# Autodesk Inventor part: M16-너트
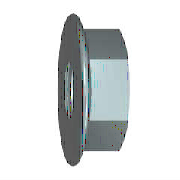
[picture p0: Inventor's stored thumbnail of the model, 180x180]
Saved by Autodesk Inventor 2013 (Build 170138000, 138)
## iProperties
IsCustomPart: 0
Company: 한국ATC센터
Created: 2009-02
Part Number: M16-너트
Material: Steel, Mild
Description: 플랜지붙이 6각 너트
Document SubType Name: Modeling
Standard: JIS B 1190
Designer: KYOUNG IL JANG
Standards Organization: JIS
Language: ko-KR
Size Designation: M 16
Categories: <MemberInstance><Categories><Category DisplayName="조임쇠" InternalName="e4da775c-781d-43d5-af7c-5136215cf5a6" Mnemonic="FSTN"><Category DisplayName="너트" InternalN
Density: 1 g/cm^3
Author: KYOUNG IL JANG
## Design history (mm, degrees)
sketch "스케치1"
  geometry: L1 (-3.414, 0)-(18.069, 0) reference; L2 (6.015, 11)-(3.359, 15.6); L3 (6.015, 11)-(15, 11); L4 (15, 11)-(15, 0); L5 (6.015, 11)-(6.015, 0); L6 (0, -3.378)-(0, 20.266) reference; A1 r 1.8 centre (1.8, 14.7) between (3.359, 15.6) and (0, 14.7); 1 further point
  constraints: 8 end point, 3 point on line, 2 perpendicular, 2 point on circle, 2 tangent, 1 centre point, 1 parallel
  dimensions: "d2" = 22 diameter of L3 L1 (= SW); "d4" = 33 dimension on A1 L1 (= LADI); "d5" = 1.8 radius of A1 (= PHH); "d15" = 15 distance between parallel lines of L4 L6 (= KOH); "d16" = 30 deg angle of L6 L2 (= KEWI)
revolve "링" sketch "스케치1" stored, may be unused: angle "d8" = 90 deg
sketch "스케치2"
  geometry: L1 (-11, -6.351)-(-11, 6.351); L2 (-11, 6.351)-(0, 12.702); L3 (0, 12.702)-(11, 6.351); L4 (11, 6.351)-(11, -6.351); L5 (11, -6.351)-(0, -12.702); L6 (0, -12.702)-(-11, -6.351); C1 r 4.9 at (0, 0); C2 r 14.7 at (0, 0) reference; 1 further point
  constraints: 12 end point, 1 centre point, 1 coincident, 1 vertical, 11 other
  dimensions: "d6" = 25.40341 distance of L5.end L2.end (= 1.1547 x SW)
extrude "본체" join sketch "스케치2" distance "d7" = 15 (= KOH); taper "d9" = 0 deg
sketch "스케치3"
  geometry: L1 (5.032, 12.702)-(15, 12.702) reference; L2 (15, 6.351)-(15, 12.702) reference; L3 (0, -14.7)-(0, 14.7) reference; L4 (-3, 0)-(18, 0) reference; L5 (14.018, 12.702)-(15, 11)
  constraints: 2 end point, 2 point on line
  dimensions: "d10" = 30 deg angle of L2 L5 (= ANG1); "d11" = 22 diameter of L5.end L4 (= SW0)
revolve "모따기1" sketch "스케치3" stored, may be unused: angle "d24" = 90 deg
sketch "스케치4"
  geometry: C1 r 14.7 at (0, 0) reference; 1 further point
  constraints: 1 coincident
hole "스레드" sketch "스케치4" at (0, 0) diameter "d25" = 13.835; stored, may be unused: countersink angle "d29" = 82 deg, drill point angle "d31" = 118 deg; dims "d26" = 6, "d27" = 4, "d28" = 2, "d30" = 8
workaxis "Work Axis1"
workplane "Work Plane1"
body "Solid1"
chamfer "모따기2" distance "d12" = 1.08253 (= -0.5 x GD1 + 0.5 x NND); stored, may be unused: angle "d13" = 30 deg, second distance "d46" = 1.08253 (= -0.5 x GD1 + 0.5 x NND)
chamfer "모따기3" distance "d51" = 1.08253 (= -0.5 x GD1 + 0.5 x NND); stored, may be unused: second distance "d52" = 2, angle "d53" = 45 deg
other parameters: "ANG1" = 30 deg [user parameter; used in 1 equation term], "KEWI" = 30 deg [user parameter; used in 1 equation term], "NND" = 16 [user parameter; used in 3 equation terms], "LADI" = 33 [user parameter; used in 2 equation terms], "SW" = 22 [user parameter; used in 4 equation terms], "PHH" = 1.8 [user parameter; used in 2 equation terms], "KOH" = 15 [user parameter; used in 2 equation terms], "SW0" = 22 (= SW) [user parameter; used in 1 equation term], "GD1" = 13.83494 (computed from THREADDIA, PTC, TOA) [user parameter; used in 3 equation terms], "d1" = 33 (= LADI), "d3" = 1.8 (= PHH), "d45" = 0, "d47" = 0, "d49" = 0, "d54" = 0, "GUL" = 1.08253 (= 0.541266 x PTC) [user parameter], "TPU" = 5 (computed from PTC) [user parameter], "RR" = 2 [user parameter], "THREADDIA" = 16 [user parameter; used in 1 equation term], "TOA" = 30 deg [user parameter; used in 1 equation term], "PTC" = 2 [user parameter; used in 4 equation terms], "GAL" = 1.08253 (= 0.541266 x PTC) [user parameter], "E0" = 25.41 (= 1.155 x SW) [user parameter]
